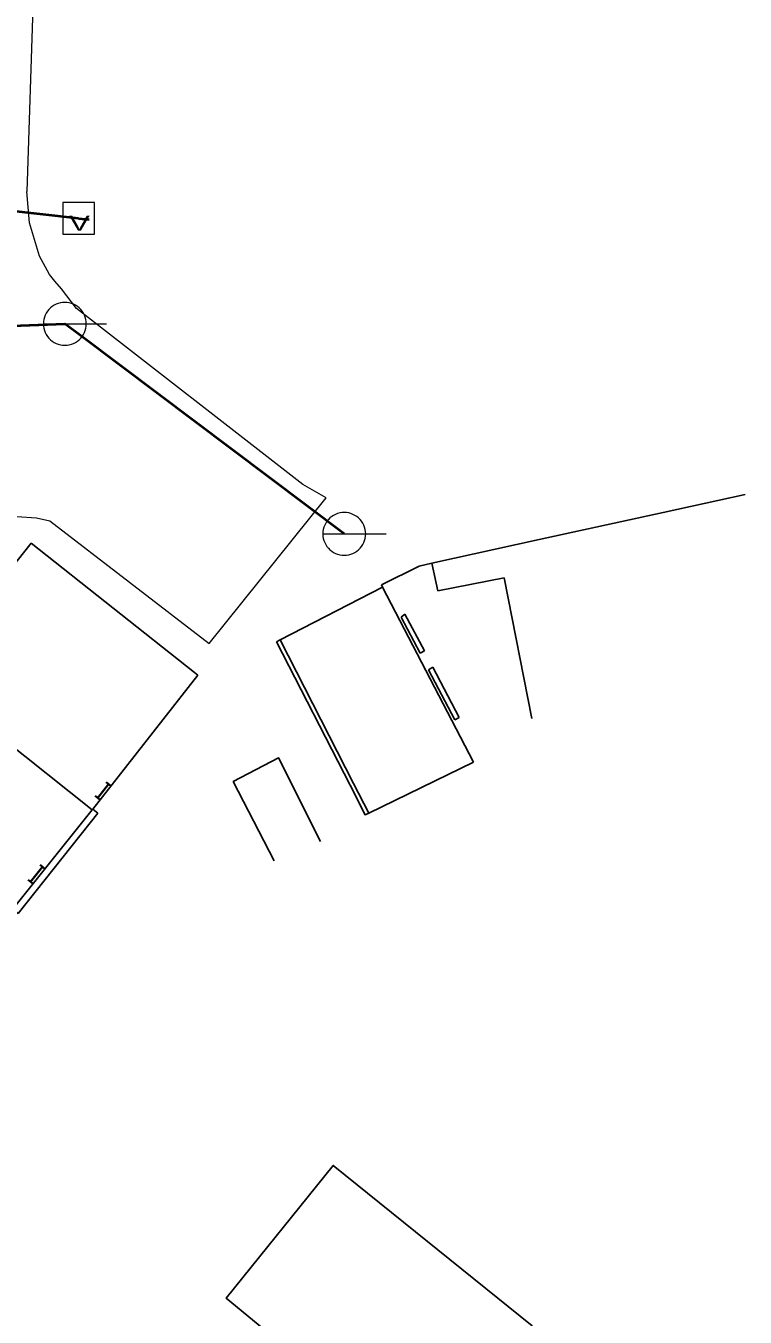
# Model space of a CAD drawing. Extents: x -968691 to -140888, y -1376050 to -879856.
# Drawn here: x -646115.6 to -646081.7, y -1062536.6 to -1062475.8 of the extents above; entities that cross this region are included whole.
import ezdxf
from ezdxf.enums import TextEntityAlignment as Align

# ---------------------------------------------------------------- set-up
doc = ezdxf.new("R2010")
doc.units = 0
doc.header["$LTSCALE"] = 4.8
for name, pattern in [('DOT_DASHED', [7.7, 5, -1.2, 0.3, -1.2]), ('DOTTED', [1.5, 0.3, -1.2]), ('LONG_DASHED', [7.5, 6, -1.5]), ('MEDIUM_DASHED', [4.5, 3, -1.5])]:
    doc.linetypes.add(name, pattern=pattern)
doc.layers.add('1', color=7, linetype='Continuous', lineweight=13)

msp = doc.modelspace()

# ---------------------------------------------------------------- linework, layer by layer
at = {"layer": '1'}
for p, q in [((-646114.71, -1062459.64), (-646115.51, -1062483.63)), ((-646113.07, -1062484.9), (-646116.58, -1062484.52)), ((-646113.07, -1062484.9), (-646112.573, -1062484.954)), ((-646114.728, -1062489.86), (-646111.752, -1062489.86)), ((-646112.918, -1062490.457), (-646113.72, -1062489.86)), ((-646100.57, -1062499.74), (-646112.918, -1062490.457)), ((-646106.935, -1062504.9), (-646101.423, -1062498.04)), ((-646114.42, -1062499.13), (-646106.935, -1062504.9)), ((-646101.578, -1062499.74), (-646098.602, -1062499.74))]:
    msp.add_line(p, q, dxfattribs=at)
at = {"layer": '1', "linetype": 'LONG_DASHED', "lineweight": 40}
for p, q in [((-646113.07, -1062484.9), (-646116.58, -1062484.52)), ((-646112.918, -1062490.457), (-646113.72, -1062489.86)), ((-646100.57, -1062499.74), (-646112.918, -1062490.457))]:
    msp.add_line(p, q, dxfattribs=at)
at = {"layer": '1', "linetype": 'DOTTED', "lineweight": 40}
msp.add_line((-646113.07, -1062484.9), (-646112.573, -1062484.954), dxfattribs=at)
at = {"layer": '1', "lineweight": 25}
for p, q in [((-646115.3, -1062500.17), (-646120.26, -1062506.41)), ((-646107.622, -1062506.261), (-646115.3, -1062500.17)), ((-646103.752, -1062504.817), (-646103.579, -1062504.72)), ((-646107.46, -1062506.39), (-646112.399, -1062512.681)), ((-646107.46, -1062506.39), (-646107.622, -1062506.261)), ((-646112.43, -1062512.72), (-646116.13, -1062517.35)), ((-646112.399, -1062512.681), (-646112.43, -1062512.72))]:
    msp.add_line(p, q, dxfattribs=at)
at = {"layer": '1', "linetype": 'MEDIUM_DASHED', "lineweight": 25}
for p, q in [((-646096.452, -1062501.113), (-646097.05, -1062501.251)), ((-646103.579, -1062504.72), (-646098.767, -1062502.239)), ((-646094.491, -1062510.478), (-646098.767, -1062502.239)), ((-646116.69, -1062509.33), (-646112.43, -1062512.72)), ((-646099.415, -1062512.876), (-646094.491, -1062510.478)), ((-646112.399, -1062512.681), (-646112.16, -1062512.87))]:
    msp.add_line(p, q, dxfattribs=at)
at = {"layer": '1', "lineweight": 35}
for p, q in [((-646111.66, -1062511.506), (-646112.17, -1062512.15)), ((-646111.543, -1062511.6), (-646111.776, -1062511.413)), ((-646112.053, -1062512.244), (-646112.286, -1062512.057)), ((-646114.767, -1062515.404), (-646115.331, -1062516.109)), ((-646114.66, -1062515.49), (-646114.883, -1062515.311)), ((-646115.214, -1062516.203), (-646115.447, -1062516.016))]:
    msp.add_line(p, q, dxfattribs=at)
at = {"layer": '1', "linetype": 'LONG_DASHED', "lineweight": 40}
msp.add_lwpolyline([(-646117.282, -1062474.217), (-646117.5, -1062490), (-646113.72, -1062489.86)], dxfattribs=at)
at = {"layer": '1', "lineweight": 35}
msp.add_lwpolyline([(-646117.282, -1062474.217), (-646117.5, -1062490), (-646113.72, -1062489.86)], dxfattribs=at)
at = {"layer": '1'}
for points in [[(-646113.176, -1062489.132), (-646113.882, -1062488.212), (-646114.185, -1062487.851), (-646114.445, -1062487.541), (-646114.906, -1062486.67), (-646115.383, -1062485.106), (-646115.51, -1062483.63)], [(-646101.423, -1062498.04), (-646102.52, -1062497.42), (-646113.176, -1062489.132)], [(-646118.62, -1062499.61), (-646117.853, -1062499.202), (-646117.17, -1062498.99), (-646116.298, -1062498.943), (-646115.974, -1062498.926), (-646115.059, -1062498.989), (-646114.42, -1062499.13)]]:
    msp.add_lwpolyline(points, dxfattribs=at)
for points in [[(-646113.82, -1062485.65), (-646112.32, -1062485.65), (-646112.32, -1062484.15), (-646113.82, -1062484.15)], [(-646113.72, -1062488.852), (-646113.825, -1062488.858), (-646113.929, -1062488.874), (-646114.031, -1062488.902), (-646114.13, -1062488.94), (-646114.224, -1062488.987), (-646114.312, -1062489.045), (-646114.394, -1062489.111), (-646114.469, -1062489.186), (-646114.535, -1062489.268), (-646114.593, -1062489.356), (-646114.64, -1062489.45), (-646114.678, -1062489.549), (-646114.706, -1062489.651), (-646114.722, -1062489.755), (-646114.728, -1062489.86), (-646114.722, -1062489.965), (-646114.706, -1062490.07), (-646114.678, -1062490.172), (-646114.64, -1062490.27), (-646114.593, -1062490.364), (-646114.535, -1062490.453), (-646114.469, -1062490.535), (-646114.394, -1062490.609), (-646114.312, -1062490.675), (-646114.224, -1062490.733), (-646114.13, -1062490.781), (-646114.031, -1062490.819), (-646113.929, -1062490.846), (-646113.825, -1062490.862), (-646113.72, -1062490.868), (-646113.615, -1062490.862), (-646113.51, -1062490.846), (-646113.408, -1062490.819), (-646113.31, -1062490.781), (-646113.216, -1062490.733), (-646113.127, -1062490.675), (-646113.045, -1062490.609), (-646112.971, -1062490.535), (-646112.905, -1062490.453), (-646112.847, -1062490.364), (-646112.799, -1062490.27), (-646112.761, -1062490.172), (-646112.734, -1062490.07), (-646112.718, -1062489.965), (-646112.712, -1062489.86), (-646112.718, -1062489.755), (-646112.734, -1062489.651), (-646112.761, -1062489.549), (-646112.799, -1062489.45), (-646112.847, -1062489.356), (-646112.905, -1062489.268), (-646112.971, -1062489.186), (-646113.045, -1062489.111), (-646113.127, -1062489.045), (-646113.216, -1062488.987), (-646113.31, -1062488.94), (-646113.408, -1062488.902), (-646113.51, -1062488.874), (-646113.615, -1062488.858)], [(-646100.57, -1062498.732), (-646100.675, -1062498.738), (-646100.779, -1062498.754), (-646100.881, -1062498.782), (-646100.98, -1062498.82), (-646101.074, -1062498.867), (-646101.162, -1062498.925), (-646101.244, -1062498.991), (-646101.319, -1062499.066), (-646101.385, -1062499.148), (-646101.443, -1062499.236), (-646101.49, -1062499.33), (-646101.528, -1062499.429), (-646101.556, -1062499.531), (-646101.572, -1062499.635), (-646101.578, -1062499.74), (-646101.572, -1062499.845), (-646101.556, -1062499.95), (-646101.528, -1062500.052), (-646101.49, -1062500.15), (-646101.443, -1062500.244), (-646101.385, -1062500.333), (-646101.319, -1062500.415), (-646101.244, -1062500.489), (-646101.162, -1062500.555), (-646101.074, -1062500.613), (-646100.98, -1062500.661), (-646100.881, -1062500.699), (-646100.779, -1062500.726), (-646100.675, -1062500.742), (-646100.57, -1062500.748), (-646100.465, -1062500.742), (-646100.36, -1062500.726), (-646100.258, -1062500.699), (-646100.16, -1062500.661), (-646100.066, -1062500.613), (-646099.977, -1062500.555), (-646099.895, -1062500.489), (-646099.821, -1062500.415), (-646099.755, -1062500.333), (-646099.697, -1062500.244), (-646099.649, -1062500.15), (-646099.611, -1062500.052), (-646099.584, -1062499.95), (-646099.568, -1062499.845), (-646099.562, -1062499.74), (-646099.568, -1062499.635), (-646099.584, -1062499.531), (-646099.611, -1062499.429), (-646099.649, -1062499.33), (-646099.697, -1062499.236), (-646099.755, -1062499.148), (-646099.821, -1062499.066), (-646099.895, -1062498.991), (-646099.977, -1062498.925), (-646100.066, -1062498.867), (-646100.16, -1062498.82), (-646100.258, -1062498.782), (-646100.36, -1062498.754), (-646100.465, -1062498.738)]]:
    msp.add_lwpolyline(points, close=True, dxfattribs=at)
at = {"layer": '1', "lineweight": 25}
for points in [[(-646081.702, -1062497.89), (-646085.567, -1062498.735), (-646091.4, -1062500.009), (-646096.452, -1062501.113)], [(-646099.415, -1062512.876), (-646099.59, -1062512.945), (-646100.299, -1062511.561), (-646103.752, -1062504.817)], [(-646103.866, -1062515.119), (-646105.796, -1062511.387), (-646103.663, -1062510.279), (-646101.692, -1062514.205)], [(-646103.828, -1062537.582), (-646106.13, -1062535.68), (-646101.09, -1062529.44), (-646091.73, -1062536.98), (-646095.798, -1062541.991), (-646096.165, -1062542.444)]]:
    msp.add_lwpolyline(points, dxfattribs=at)
at = {"layer": '1', "linetype": 'DOT_DASHED', "lineweight": 25}
for points in [[(-646091.736, -1062508.429), (-646093.051, -1062501.803), (-646096.159, -1062502.415), (-646096.452, -1062501.113)], [(-646103.579, -1062504.72), (-646100.129, -1062511.477), (-646099.415, -1062512.876)]]:
    msp.add_lwpolyline(points, dxfattribs=at)
at = {"layer": '1', "linetype": 'MEDIUM_DASHED', "lineweight": 25}
for points in [[(-646097.05, -1062501.251), (-646098.824, -1062502.13), (-646098.767, -1062502.239)], [(-646112.16, -1062512.87), (-646115.92, -1062517.6), (-646116.17, -1062517.4)]]:
    msp.add_lwpolyline(points, dxfattribs=at)
at = {"layer": '1', "linetype": 'DOT_DASHED', "lineweight": 25}
for points in [[(-646097.712, -1062503.52), (-646097.899, -1062503.658), (-646097.002, -1062505.342), (-646096.799, -1062505.234)], [(-646096.405, -1062506), (-646095.162, -1062508.376), (-646095.37, -1062508.485), (-646096.6, -1062506.134)]]:
    msp.add_lwpolyline(points, close=True, dxfattribs=at)

# ---------------------------------------------------------------- texts
at = {"layer": '1', "width": 1.55}
msp.add_text('V', height=0.7, dxfattribs=at).set_placement((-646113.031, -1062485.479), align=Align.CENTER)

doc.saveas('drawing.dxf')
